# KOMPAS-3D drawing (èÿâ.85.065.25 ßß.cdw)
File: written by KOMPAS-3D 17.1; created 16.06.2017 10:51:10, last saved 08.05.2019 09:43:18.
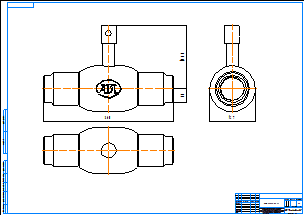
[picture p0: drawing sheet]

Sheet 1: A1, landscape

Title block, sheet 1: name: КШГ.85.065.25 сс; material: Внимание! Данный продукт является объектом авторского права ООО «Торговый Дом АДЛ». / Запрещается изменение, копирование, распространение / (в том числе путем копирования на другие сайты и ресурсы в Интернете) / или любое иное использование информации и объектов без предварительного / согласия правообладателя (ООО «Торговый Дом АДЛ»).; scale: 1:1; sheets: 1; organisation: ООО "Торговый дом АДЛ"; sheet format: A1; stored path: C:\Users\tra\Desktop\2д чертежи\Шаровые краны БИВАЛ\КШ_Бивал_серия_82_85\KOMPAS 2D\КШГ.85.065.25 сс.cdw

Views: Спереди 1, Проекционный вид 2, Проекционный вид 3
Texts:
  Klimkovich
  ADL
Dimensions and other numbers on the sheet: 360; 176,8; 38; 127; 1:1; 1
